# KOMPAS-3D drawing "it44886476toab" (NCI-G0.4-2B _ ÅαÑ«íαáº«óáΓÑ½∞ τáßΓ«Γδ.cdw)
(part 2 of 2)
  Кривая без истории:10764
  Кривая без истории:10765
  Кривая без истории:10766
  Кривая без истории:10767
  Кривая без истории:10768
  Кривая без истории:10769
  Кривая без истории:10770
  Кривая без истории:10771
  Кривая без истории:10772
  Кривая без истории:10773
  Кривая без истории:10774
  Кривая без истории:10775
  Кривая без истории:10776
  Кривая без истории:10777
  Кривая без истории:10778
  Кривая без истории:10779
  Кривая без истории:10780
  Кривая без истории:10781
  Кривая без истории:10782
  Кривая без истории:10783
  Кривая без истории:10784
  Кривая без истории:10785
  Кривая без истории:10786
  Кривая без истории:10787
  Кривая без истории:10788
  Кривая без истории:10789
  Кривая без истории:10790
  Кривая без истории:10791
  Кривая без истории:10792
  Кривая без истории:10793
  Кривая без истории:10794
  Кривая без истории:10795
  Кривая без истории:10796
  Кривая без истории:10797
  Кривая без истории:10798
  Кривая без истории:10799
  Кривая без истории:10800
  Кривая без истории:10801
  Кривая без истории:10802
  Кривая без истории:10803
  Кривая без истории:10804
  Кривая без истории:10805
  Кривая без истории:10806
  Кривая без истории:10807
  Кривая без истории:10808
  Кривая без истории:10809
  Кривая без истории:10810
  Кривая без истории:10811
  Кривая без истории:10812
  Кривая без истории:10813
  Кривая без истории:10814
  Кривая без истории:10815
  Кривая без истории:10816
  Кривая без истории:10817
  Кривая без истории:10818
  Кривая без истории:10819
  Кривая без истории:10820
  Кривая без истории:10821
  Кривая без истории:10822
  Кривая без истории:10823
  Кривая без истории:10824
  Кривая без истории:10825
  Кривая без истории:10826
  Кривая без истории:10827
  Кривая без истории:10828
  Кривая без истории:10829
  Кривая без истории:10830
  Кривая без истории:10831
  Кривая без истории:10832
  Кривая без истории:10833
  Кривая без истории:10834
  Кривая без истории:10835
  Кривая без истории:10836
  Кривая без истории:10837
  Кривая без истории:10838
  Кривая без истории:10839
  Кривая без истории:10840
  Кривая без истории:10841
  Кривая без истории:10842
  Кривая без истории:10843
  Кривая без истории:10844
  Кривая без истории:10845
  Кривая без истории:10846
  Кривая без истории:10847
  Кривая без истории:10848
  Кривая без истории:10849
  Кривая без истории:10850
  Кривая без истории:10851
  Кривая без истории:10852
  Кривая без истории:10853
  Кривая без истории:10854
  Кривая без истории:10855
  Кривая без истории:10856
  Кривая без истории:10857
  Кривая без истории:10858
  Кривая без истории:10859
  Кривая без истории:10860
  Кривая без истории:10861
  Кривая без истории:10862
  Кривая без истории:10863
  Кривая без истории:10864
  Кривая без истории:10865
  Кривая без истории:10866
  Кривая без истории:10867
  Кривая без истории:10868
  Кривая без истории:10869
  Кривая без истории:10870
  Кривая без истории:10871
  Кривая без истории:10872
  Кривая без истории:10873
  Кривая без истории:10874
  Кривая без истории:10875
  Кривая без истории:10876
  Кривая без истории:10877
  Кривая без истории:10878
  Кривая без истории:10879
  Кривая без истории:10880
  Кривая без истории:10881
  Кривая без истории:10882
  Кривая без истории:10883
  Кривая без истории:10884
  Кривая без истории:10885
  Кривая без истории:10886
  Кривая без истории:10887
  Кривая без истории:10888
  Кривая без истории:10889
  Кривая без истории:10890
  Кривая без истории:10891
  Кривая без истории:10892
  Кривая без истории:10893
  Кривая без истории:10894
  Кривая без истории:10895
  Кривая без истории:10896
  Кривая без истории:10897
  Кривая без истории:10898
  Кривая без истории:10899
  Кривая без истории:10900
  Кривая без истории:10901
  Кривая без истории:10902
  Кривая без истории:10903
  Кривая без истории:10904
  Кривая без истории:10905
  Кривая без истории:10906
  Кривая без истории:10907
  Кривая без истории:10908
  Кривая без истории:10909
  Кривая без истории:10910
  Кривая без истории:10911
  Кривая без истории:10912
  Кривая без истории:10913
  Кривая без истории:10914
  Кривая без истории:10915
  Кривая без истории:10916
  Кривая без истории:10917
  Кривая без истории:10918
  Кривая без истории:10919
  Кривая без истории:10920
  Кривая без истории:10921
  Кривая без истории:10922
  Кривая без истории:10923
  Кривая без истории:10924
  Кривая без истории:10925
  Кривая без истории:10926
  Кривая без истории:10927
  Кривая без истории:10928
  Кривая без истории:10929
  Кривая без истории:10930
  Кривая без истории:10931
  Кривая без истории:10932
  Кривая без истории:10933
  Кривая без истории:10934
  Кривая без истории:10935
  Кривая без истории:10936
  Кривая без истории:10937
  Кривая без истории:10938
  Кривая без истории:10939
  Кривая без истории:10940
  Кривая без истории:10941
  Кривая без истории:10942
  Кривая без истории:10943
  Кривая без истории:10944
  Кривая без истории:10945
  Кривая без истории:10946
  Кривая без истории:10947
  Кривая без истории:10948
  Кривая без истории:10949
  Кривая без истории:10950
  Кривая без истории:10951
  Кривая без истории:10952
  Кривая без истории:10953
  Кривая без истории:10954
  Кривая без истории:10955
  Кривая без истории:10956
  Кривая без истории:10957
  Кривая без истории:10958
  Кривая без истории:10959
  Кривая без истории:10960
  Кривая без истории:10961
  Кривая без истории:10962
  Кривая без истории:10963
  Кривая без истории:10964
  Кривая без истории:10965
  Кривая без истории:10966
  Кривая без истории:10967
  Кривая без истории:10968
  Кривая без истории:10969
  Кривая без истории:10970
  Кривая без истории:10971
  Кривая без истории:10972
  Кривая без истории:10973
  Кривая без истории:10974
  Кривая без истории:10975
  Кривая без истории:10976
  Кривая без истории:10977
  Кривая без истории:10978
  Кривая без истории:10979
  Кривая без истории:10980
  Кривая без истории:10981
  Кривая без истории:10982
  Кривая без истории:10983
  Кривая без истории:10984
  Кривая без истории:10985
  Кривая без истории:10986
  Кривая без истории:10987
  Кривая без истории:10988
  Кривая без истории:10989
  Кривая без истории:10990
  Кривая без истории:10991
  Кривая без истории:10992
  Кривая без истории:10993
  Кривая без истории:10994
  Кривая без истории:10995
  Кривая без истории:10996
  Кривая без истории:10997
  Кривая без истории:10998
  Кривая без истории:10999
  Кривая без истории:11000
  Кривая без истории:11001
  Кривая без истории:11002
  Кривая без истории:11003
  Кривая без истории:11004
  Кривая без истории:11005
  Кривая без истории:11006
  Кривая без истории:11007
  Кривая без истории:11008
  Кривая без истории:11009
  Кривая без истории:11010
  Кривая без истории:11011
  Кривая без истории:11012
  Кривая без истории:11013
  Кривая без истории:11014
  Кривая без истории:11015
  Кривая без истории:11016
  Кривая без истории:11017
  Кривая без истории:11018
  Кривая без истории:11019
  Кривая без истории:11020
  Кривая без истории:11021
  Кривая без истории:11022
  Кривая без истории:11023
  Кривая без истории:11024
  Кривая без истории:11025
  Кривая без истории:11026
  Кривая без истории:11027
  Кривая без истории:11028
  Кривая без истории:11029
  Кривая без истории:11030
  Кривая без истории:11031
  Кривая без истории:11032
  Кривая без истории:11033
  Кривая без истории:11034
  Кривая без истории:11035
  Кривая без истории:11036
  Кривая без истории:11037
  Кривая без истории:11038
  Кривая без истории:11039
  Кривая без истории:11040
  Кривая без истории:11041
  Кривая без истории:11042
  Кривая без истории:11043
  Кривая без истории:11044
  Кривая без истории:11045
  Кривая без истории:11046
  Кривая без истории:11047
  Кривая без истории:11048
  Кривая без истории:11049
  Кривая без истории:11050
  Кривая без истории:11051
  Кривая без истории:11052
  Кривая без истории:11053
  Кривая без истории:11054
  Кривая без истории:11055
  Кривая без истории:11056
  Кривая без истории:11057
  Кривая без истории:11058
  Кривая без истории:11059
  Кривая без истории:11060
  Кривая без истории:11061
  Кривая без истории:11062
  Кривая без истории:11063
  Кривая без истории:11064
  Кривая без истории:11065
  Кривая без истории:11066
  Кривая без истории:11067
  Кривая без истории:11068
  Кривая без истории:11069
  Кривая без истории:11070
  Кривая без истории:11071
  Кривая без истории:11072
  Кривая без истории:11073
  Кривая без истории:11074
  Кривая без истории:11075
  Кривая без истории:11076
  Кривая без истории:11077
  Кривая без истории:11078
  Кривая без истории:11079
  Кривая без истории:11080
  Кривая без истории:11081
  Кривая без истории:11082
  Кривая без истории:11083
  Кривая без истории:11084
  Кривая без истории:11085
  Кривая без истории:11086
  Кривая без истории:11087
  Кривая без истории:11088
  Кривая без истории:11089
  Кривая без истории:11090
  Кривая без истории:11091
  Кривая без истории:11092
  Кривая без истории:11093
  Кривая без истории:11094
  Кривая без истории:11095
  Кривая без истории:11096
  Кривая без истории:11097
  Кривая без истории:11098
  Кривая без истории:11099
  Кривая без истории:11100
  Кривая без истории:11101
  Кривая без истории:11102
  Кривая без истории:11103
  Кривая без истории:11104
  Кривая без истории:11105
  Кривая без истории:11106
  Кривая без истории:11107
  Кривая без истории:11108
  Кривая без истории:11109
  Кривая без истории:11110
  Кривая без истории:11111
  Кривая без истории:11112
  Кривая без истории:11113
  Кривая без истории:11114
  Кривая без истории:11115
  Кривая без истории:11116
  Кривая без истории:11117
  Кривая без истории:11118
  Кривая без истории:11119
  Кривая без истории:11120
  Кривая без истории:11121
  Кривая без истории:11122
  Кривая без истории:11123
  Кривая без истории:11124
  Кривая без истории:11125
  Кривая без истории:11126
  Кривая без истории:11127
  Кривая без истории:11128
  Кривая без истории:11129
  Кривая без истории:11130
  Кривая без истории:11131
  Кривая без истории:11132
  Кривая без истории:11133
  Кривая без истории:11134
  Кривая без истории:11135
  Кривая без истории:11136
  Кривая без истории:11137
  Кривая без истории:11138
  Кривая без истории:11139
  Кривая без истории:11140
  Кривая без истории:11141
  Кривая без истории:11142
  Кривая без истории:11143
  Кривая без истории:11144
  Кривая без истории:11145
  Кривая без истории:11146
  Кривая без истории:11147
  Кривая без истории:11148
  Кривая без истории:11149
  Кривая без истории:11150
  Кривая без истории:11151
  Кривая без истории:11152
  Кривая без истории:11153
  Кривая без истории:11154
  Кривая без истории:11155
  Кривая без истории:11156
  Кривая без истории:11157
  Кривая без истории:11158
  Кривая без истории:11159
  Кривая без истории:11160
  Кривая без истории:11161
  Кривая без истории:11162
  Кривая без истории:11163
  Кривая без истории:11164
  Кривая без истории:11165
  Кривая без истории:11166
  Кривая без истории:11167
  Кривая без истории:11168
  Кривая без истории:11169
  Кривая без истории:11170
  Кривая без истории:11171
  Кривая без истории:11172
  Кривая без истории:11173
  Кривая без истории:11174
  Кривая без истории:11175
  Кривая без истории:11176
  Кривая без истории:11177
  Кривая без истории:11178
  Кривая без истории:11179
  Кривая без истории:11180
  Кривая без истории:11181
  Кривая без истории:11182
  Кривая без истории:11183
  Кривая без истории:11184
  Кривая без истории:11185
  Кривая без истории:11186
  Кривая без истории:11187
  Кривая без истории:11188
  Кривая без истории:11189
  Кривая без истории:11190
  Кривая без истории:11191
  Кривая без истории:11192
  Кривая без истории:11193
  Кривая без истории:11194
  Кривая без истории:11195
  Кривая без истории:11196
  Кривая без истории:11197
  Кривая без истории:11198
  Кривая без истории:11199
  Кривая без истории:11200
  Кривая без истории:11201
  Кривая без истории:11202
  Кривая без истории:11203
  Кривая без истории:11204
  Кривая без истории:11205
  Кривая без истории:11206
  Кривая без истории:11207
  Кривая без истории:11208
  Кривая без истории:11209
  Кривая без истории:11210
  Кривая без истории:11211
  Кривая без истории:11212
  Кривая без истории:11213
  Кривая без истории:11214
  Кривая без истории:11215
  Кривая без истории:11216
  Кривая без истории:11217
  Кривая без истории:11218
  Кривая без истории:11219
  Кривая без истории:11220
  Кривая без истории:11221
  Кривая без истории:11222
  Кривая без истории:11223
  Кривая без истории:11224
  Кривая без истории:11225
  Кривая без истории:11226
  Кривая без истории:11227
  Кривая без истории:11228
  Кривая без истории:11229
  Кривая без истории:11230
  Кривая без истории:11231
  Кривая без истории:11232
  Кривая без истории:11233
  Кривая без истории:11234
  Кривая без истории:11235
  Кривая без истории:11236
  Кривая без истории:11237
  Кривая без истории:11238
  Кривая без истории:11239
  Кривая без истории:11240
  Кривая без истории:11241
  Кривая без истории:11242
  Кривая без истории:11243
  Кривая без истории:11244
  Кривая без истории:11245
  Кривая без истории:11246
  Кривая без истории:11247
  Кривая без истории:11248
  Кривая без истории:11249
  Кривая без истории:11250
  Кривая без истории:11251
  Кривая без истории:11252
  Кривая без истории:11253
  Кривая без истории:11254
  Кривая без истории:11255
  Кривая без истории:11256
  Кривая без истории:11257
  Кривая без истории:11258
  Кривая без истории:11259
  Кривая без истории:11260
  Кривая без истории:11261
  Кривая без истории:11262
  Кривая без истории:11263
  Кривая без истории:11264
  Кривая без истории:11265
  Кривая без истории:11266
  Кривая без истории:11267
  Кривая без истории:11268
  Кривая без истории:11269
  Кривая без истории:11270
  Кривая без истории:11271
  Кривая без истории:11272
  Кривая без истории:11273
  Кривая без истории:11274
  Кривая без истории:11275
  Кривая без истории:11276
  Кривая без истории:11277
  Кривая без истории:11278
  Кривая без истории:11279
  Кривая без истории:11280
  Кривая без истории:11281
  Кривая без истории:11282
  Кривая без истории:11283
  Кривая без истории:11284
  Кривая без истории:11285
  Кривая без истории:11286
  Кривая без истории:11287
  Кривая без истории:11288
  Кривая без истории:11289
  Кривая без истории:11290
  Кривая без истории:11291
  Кривая без истории:11292
  Кривая без истории:11293
  Кривая без истории:11294
  Кривая без истории:11295
  Кривая без истории:11296
  Кривая без истории:11297
  Кривая без истории:11298
  Кривая без истории:11299
  Кривая без истории:11300
  Кривая без истории:11301
  Кривая без истории:11302
  Кривая без истории:11303
  Кривая без истории:11304
  Кривая без истории:11305
  Кривая без истории:11306
  Кривая без истории:11307
  Кривая без истории:11308
  Кривая без истории:11309
  Кривая без истории:11310
  Кривая без истории:11311
  Кривая без истории:11312
  Кривая без истории:11313
  Кривая без истории:11314
  Кривая без истории:11315
  Кривая без истории:11316
  Кривая без истории:11317
  Кривая без истории:11318
  Кривая без истории:11319
  Кривая без истории:11320
  Кривая без истории:11321
  Кривая без истории:11322
  Кривая без истории:11323
  Кривая без истории:11324
  Кривая без истории:11325
  Кривая без истории:11326
  Кривая без истории:11327
  Кривая без истории:11328
  Кривая без истории:11329
  Кривая без истории:11330
  Кривая без истории:11331
  Кривая без истории:11332
  Кривая без истории:11333
  Кривая без истории:11334
  Кривая без истории:11335
  Кривая без истории:11336
  Кривая без истории:11337
  Кривая без истории:11338
  Кривая без истории:11339
  Кривая без истории:11340
  Кривая без истории:11341
  Кривая без истории:11342
  Кривая без истории:11343
  Кривая без истории:11344
  Кривая без истории:11345
  Кривая без истории:11346
  Кривая без истории:11347
  Кривая без истории:11348
  Кривая без истории:11349
  Кривая без истории:11350
  Кривая без истории:11351
  Кривая без истории:11352
  Кривая без истории:11353
  Кривая без истории:11354
  Кривая без истории:11355
  Кривая без истории:11356
  Кривая без истории:11357
  Кривая без истории:11358
  Кривая без истории:11359
  Кривая без истории:11360
  Кривая без истории:11361
  Кривая без истории:11362
  Кривая без истории:11363
  Кривая без истории:11364
  Кривая без истории:11365
  Кривая без истории:11366
  Кривая без истории:11367
  Кривая без истории:11368
  Кривая без истории:11369
  Кривая без истории:11370
  Кривая без истории:11371
  Кривая без истории:11372
  Кривая без истории:11373
  Кривая без истории:11374
  Кривая без истории:11375
  Кривая без истории:11376
  Кривая без истории:11377
  Кривая без истории:11378
  Кривая без истории:11379
  Кривая без истории:11380
  Кривая без истории:11381
  Кривая без истории:11382
  Кривая без истории:11383
  Кривая без истории:11384
  Кривая без истории:11385
  Кривая без истории:11386
  Кривая без истории:11387
  Кривая без истории:11388
  Кривая без истории:11389
  Кривая без истории:11390
  Кривая без истории:11391
  Кривая без истории:11392
  Кривая без истории:11393
  Кривая без истории:11394
  Кривая без истории:11395
  Кривая без истории:11396
  Кривая без истории:11397
  Кривая без истории:11398
  Кривая без истории:11399
  Кривая без истории:11400
  Кривая без истории:11401
  Кривая без истории:11402
  Кривая без истории:11403
  Кривая без истории:11404
  Кривая без истории:11405
  Кривая без истории:11406
  Кривая без истории:11407
  Кривая без истории:11408
  Кривая без истории:11409
  Кривая без истории:11410
  Кривая без истории:11411
  Кривая без истории:11412
  Кривая без истории:11413
  Кривая без истории:11414
  Кривая без истории:11415
  Кривая без истории:11416
  Кривая без истории:11417
  Кривая без истории:11418
  Кривая без истории:11419
  Кривая без истории:11420
  Кривая без истории:11421
  Кривая без истории:11422
  Кривая без истории:11423
  Кривая без истории:11424
  Кривая без истории:11425
  Кривая без истории:11426
  Кривая без истории:11427
  Кривая без истории:11428
  Кривая без истории:11429
  Кривая без истории:11430
  Кривая без истории:11431
  Кривая без истории:11432
  Кривая без истории:11433
  Кривая без истории:11434
  Кривая без истории:11435
  Кривая без истории:11436
  Кривая без истории:11437
  Кривая без истории:11438
  Кривая без истории:11439
  Кривая без истории:11440
  Кривая без истории:11441
  Кривая без истории:11442
  Кривая без истории:11443
  Кривая без истории:11444
  Кривая без истории:11445
  Кривая без истории:11446
  Кривая без истории:11447
  Кривая без истории:11448
  Кривая без истории:11449
  Кривая без истории:11450
  Кривая без истории:11451
  Кривая без истории:11452
  Кривая без истории:11453
  Кривая без истории:11454
  Кривая без истории:11455
  Кривая без истории:11456
  Кривая без истории:11457
  Кривая без истории:11458
  Кривая без истории:11459
  Кривая без истории:11460
  Кривая без истории:11461
  Кривая без истории:11462
  Кривая без истории:11463
  Кривая без истории:11464
  Кривая без истории:11465
  Кривая без истории:11466
  Кривая без истории:11467
  Кривая без истории:11468
  Кривая без истории:11469
  Кривая без истории:11470
  Кривая без истории:11471
  Кривая без истории:11472
  Кривая без истории:11473
  Кривая без истории:11474
  Кривая без истории:11475
  Кривая без истории:11476
  Кривая без истории:11477
  Кривая без истории:11478
  Кривая без истории:11479
  Кривая без истории:11480
  Кривая без истории:11481
  Кривая без истории:11482
  Кривая без истории:11483
  Кривая без истории:11484
  Кривая без истории:11485
  Кривая без истории:11486
  Кривая без истории:11487
  Кривая без истории:11488
  Кривая без истории:11489
  Кривая без истории:11490
  Кривая без истории:11491
  Кривая без истории:11492
  Кривая без истории:11493
  Кривая без истории:11494
  Кривая без истории:11495
  Кривая без истории:11496
  Кривая без истории:11497
  Кривая без истории:11498
  Кривая без истории:11499
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Dimensions and other numbers on the sheet: 4±1; 1:1; 1; 13.01.25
